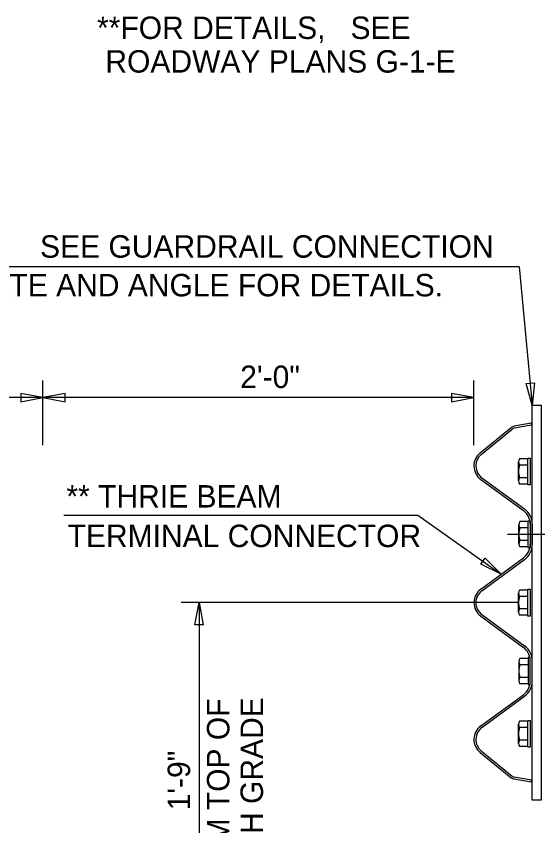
# Model space of a CAD drawing. Extents: x 0 to 22.7, y 0 to 15.7.
# Drawn here: x 15.756 to 18.176, y 5.483 to 9.243 of the extents above; entities that cross this region are included whole.
import ezdxf

# ---------------------------------------------------------------- set-up
doc = ezdxf.new("R2010")
doc.units = 0
for name, color, linetype in [('BRDG_ANNO_General-Notes', 7, 'Continuous'), ('BRDG_BASE_Dtlctrln', 7, 'Continuous'), ('BRDG_BASE_Hidden-Line', 7, 'Continuous'), ('BRDG_BASE_Obj-Line', 7, 'Continuous')]:
    doc.layers.add(name, color=color, linetype=linetype)

msp = doc.modelspace()

# ---------------------------------------------------------------- linework, layer by layer
at = {"layer": 'BRDG_ANNO_General-Notes'}
for p, q in [((18.0902, 8.0784), (15.4641, 8.0784)), ((18.0902, 8.0784), (18.1507, 7.4359)), ((15.8799, 7.2515), (15.8799, 7.5514)), ((17.8799, 7.2515), (17.8799, 7.5514)), ((18.1218, 7.537), (18.1604, 7.5406)), ((18.1507, 7.4359), (18.1218, 7.537)), ((18.1604, 7.5406), (18.1507, 7.4359)), ((15.7766, 7.4914), (15.7766, 7.4526)), ((15.8799, 7.472), (15.7766, 7.4914)), ((15.9832, 7.4914), (15.8799, 7.472)), ((15.9832, 7.4526), (15.9832, 7.4914)), ((17.7766, 7.4914), (17.7766, 7.4526)), ((17.8799, 7.472), (17.7766, 7.4914)), ((15.8799, 7.472), (14.3342, 7.472)), ((15.7766, 7.4526), (15.8799, 7.472)), ((17.8799, 7.472), (15.8799, 7.472)), ((15.8799, 7.472), (15.9832, 7.4526)), ((17.7766, 7.4526), (17.8799, 7.472)), ((15.9759, 6.9254), (17.6197, 6.9254)), ((17.6197, 6.9254), (18.007, 6.6519)), ((17.9127, 6.6974), (17.9325, 6.7256)), ((18.007, 6.6519), (17.9127, 6.6974)), ((17.9325, 6.7256), (18.007, 6.6519)), ((16.5849, 6.4159), (16.6043, 6.5193)), ((16.6043, 6.5193), (16.6043, 4.7693)), ((16.6043, 6.5193), (16.6236, 6.4159)), ((16.6236, 6.4159), (16.5849, 6.4159))]:
    msp.add_line(p, q, dxfattribs=at)
at = {"layer": 'BRDG_BASE_Dtlctrln'}
for p, q in [((18.036, 6.837), (18.3921, 6.837)), ((18.0869, 6.5193), (16.5219, 6.5193))]:
    msp.add_line(p, q, dxfattribs=at)
at = {"layer": 'BRDG_BASE_Hidden-Line'}
for p, q in [((18.1299, 7.1872), (18.0916, 7.1872)), ((18.1299, 7.1286), (18.1299, 7.1872)), ((18.0869, 7.1286), (18.0869, 7.173)), ((18.1299, 7.158), (18.0916, 7.158)), ((18.0869, 7.0844), (18.0869, 7.1286)), ((18.1299, 7.0701), (18.1299, 7.1286)), ((18.1299, 7.0994), (18.0916, 7.0994)), ((18.1299, 7.0701), (18.0916, 7.0701)), ((18.0869, 6.5193), (18.0869, 6.5636)), ((18.1299, 6.5779), (18.0916, 6.5779)), ((18.1299, 6.5486), (18.0916, 6.5486)), ((18.1299, 6.5193), (18.1299, 6.5779)), ((18.0869, 6.475), (18.0869, 6.5193)), ((18.1299, 6.4607), (18.1299, 6.5193)), ((18.1299, 6.49), (18.0916, 6.49)), ((18.1299, 6.4607), (18.0916, 6.4607)), ((18.0869, 5.9099), (18.0869, 5.9542)), ((18.1299, 5.9685), (18.0916, 5.9685)), ((18.1299, 5.9099), (18.1299, 5.9685)), ((18.0869, 5.8656), (18.0869, 5.9099)), ((18.1299, 5.9392), (18.0916, 5.9392)), ((18.1299, 5.8513), (18.1299, 5.9099)), ((18.1299, 5.8806), (18.0916, 5.8806)), ((18.1299, 5.8513), (18.0916, 5.8513))]:
    msp.add_line(p, q, dxfattribs=at)
for points in [[(18.1299, 7.1911), (18.1403, 7.1911), (18.1403, 7.0661), (18.1299, 7.0661)], [(18.1299, 6.5818), (18.1403, 6.5818), (18.1403, 6.4568), (18.1299, 6.4568)], [(18.1299, 5.9724), (18.1403, 5.9724), (18.1403, 5.8474), (18.1299, 5.8474)]]:
    msp.add_lwpolyline(points, close=True, dxfattribs=at)
for centre, radius, start, end in [((18.1123, 7.1726), 0.0254, 144.7697, 215.2303), ((18.1816, 7.1287), 0.0946, 161.9685, 198.0316), ((18.1123, 7.0847), 0.0254, 144.7697, 215.2303), ((18.1123, 6.5632), 0.0254, 144.7697, 215.2303), ((18.1816, 6.5193), 0.0946, 161.9685, 198.0316), ((18.1123, 6.4753), 0.0254, 144.7697, 215.2303), ((18.1123, 5.9539), 0.0254, 144.7697, 215.2303), ((18.1816, 5.9099), 0.0946, 161.9685, 198.0316), ((18.1123, 5.866), 0.0254, 144.7697, 215.2303)]:
    msp.add_arc(centre, radius, start, end, dxfattribs=at)
at = {"layer": 'BRDG_BASE_Obj-Line'}
for p, q in [((18.1455, 7.3526), (18.0669, 7.3388)), ((18.1471, 7.3436), (18.067, 7.3295)), ((18.1455, 7.3526), (18.1471, 7.3436)), ((17.9087, 7.2153), (18.0526, 7.3322)), ((17.9143, 7.2081), (18.0568, 7.3247)), ((17.9119, 7.0917), (18.1096, 6.9469)), ((17.9172, 7.099), (18.115, 6.9543)), ((18.1312, 6.8956), (18.0929, 6.8956)), ((18.1312, 6.837), (18.1312, 6.8956)), ((18.1416, 6.8839), (18.1416, 6.7901)), ((18.1507, 6.8839), (18.1507, 6.7901)), ((18.0883, 6.837), (18.0883, 6.8813)), ((18.1312, 6.8663), (18.0929, 6.8663)), ((18.0883, 6.7927), (18.0883, 6.837)), ((18.1312, 6.8077), (18.0929, 6.8077)), ((18.1312, 6.7784), (18.1312, 6.837)), ((18.1312, 6.7784), (18.0929, 6.7784)), ((17.9119, 6.5823), (18.1096, 6.7271)), ((17.9172, 6.5749), (18.115, 6.7197)), ((17.9119, 6.4562), (18.1096, 6.3115)), ((17.9172, 6.4636), (18.115, 6.3189)), ((18.0883, 6.2458), (18.0883, 6.2016)), ((18.1312, 6.2602), (18.0929, 6.2602)), ((18.1312, 6.2602), (18.1312, 6.2016)), ((18.1416, 6.1547), (18.1416, 6.2484)), ((18.1507, 6.1547), (18.1507, 6.2484)), ((18.1312, 6.2308), (18.0929, 6.2308)), ((18.0883, 6.2016), (18.0883, 6.1572)), ((18.1312, 6.1722), (18.0929, 6.1722)), ((18.1312, 6.2016), (18.1312, 6.143)), ((18.1312, 6.143), (18.0929, 6.143)), ((17.9119, 5.9469), (18.1096, 6.0917)), ((17.9172, 5.9395), (18.115, 6.0843)), ((17.9143, 5.8305), (18.0569, 5.7136)), ((17.9087, 5.8232), (18.0526, 5.7063)), ((18.1455, 5.6859), (18.0669, 5.6998)), ((18.1471, 5.6949), (18.067, 5.709)), ((18.1455, 5.6859), (18.1471, 5.6949))]:
    msp.add_line(p, q, dxfattribs=at)
for points in [[(18.1507, 7.4359), (18.1924, 7.4359), (18.1924, 5.6026), (18.1507, 5.6026)], [(18.1312, 6.8995), (18.1417, 6.8995), (18.1417, 6.7745), (18.1312, 6.7745)], [(18.1312, 6.1391), (18.1417, 6.1391), (18.1417, 6.2641), (18.1312, 6.2641)]]:
    msp.add_lwpolyline(points, close=True, dxfattribs=at)
for centre, radius, start, end in [((18.0723, 7.308), 0.0312, 99.9556, 129.1223), ((18.0709, 7.3077), 0.0221, 99.8748, 129.437), ((17.958, 7.1547), 0.0781, 129.1013, 233.7872), ((17.958, 7.1547), 0.069, 129.3016, 233.7787), ((18.0635, 6.8839), 0.0781, 0, 53.7872), ((18.0635, 6.8839), 0.0872, 0, 53.8142), ((18.1137, 6.8809), 0.0254, 144.7697, 215.2303), ((18.1829, 6.837), 0.0946, 161.9685, 198.0316), ((18.1137, 6.7931), 0.0254, 144.7697, 215.2303), ((18.0635, 6.7901), 0.0781, 306.2128, 0), ((18.0635, 6.7901), 0.0872, 306.1858, 0), ((17.958, 6.5193), 0.0781, 126.2128, 233.7872), ((17.958, 6.5193), 0.069, 126.2213, 233.7787), ((18.0635, 6.2485), 0.0872, 360, 53.8142), ((18.0635, 6.2485), 0.0781, 0, 53.7872), ((18.1137, 6.2455), 0.0254, 144.7697, 215.2303), ((18.1829, 6.2016), 0.0946, 161.9684, 198.0315), ((18.1137, 6.1576), 0.0254, 144.7697, 215.2303), ((18.0635, 6.1547), 0.0781, 306.2128, 0), ((18.0635, 6.1547), 0.0872, 306.1858, 0), ((17.958, 5.8839), 0.0781, 126.2128, 230.8987), ((17.958, 5.8839), 0.069, 126.2213, 230.6984), ((18.0723, 5.7306), 0.0312, 230.9446, 260.0808), ((18.0709, 5.7308), 0.0221, 230.8237, 259.9392)]:
    msp.add_arc(centre, radius, start, end, dxfattribs=at)

# ---------------------------------------------------------------- texts
at = {"layer": 'BRDG_ANNO_General-Notes'}
for s, height, p in [('**FOR DETAILS,   SEE', 0.104167, (16.1307, 9.1374)), (' ROADWAY PLANS G-1-E', 0.104167, (16.1307, 8.9812)), ('SEE GUARDRAIL CONNECTION', 0.104167, (15.8662, 8.1215)), ('PLATE AND ANGLE FOR DETAILS.', 0.104167, (15.4609, 7.9419)), ('2\'-0"', 0.10417, (16.7952, 7.5161)), ('** THRIE BEAM', 0.104167, (15.9885, 6.9611)), ('TERMINAL CONNECTOR', 0.104167, (15.9941, 6.7774))]:
    msp.add_text(s, height=height, dxfattribs=at).set_placement(p)
for s, height, p in [('FROM TOP OF', 0.104167, (16.7449, 5.1068)), ('FINISH GRADE', 0.104167, (16.9011, 5.0891)), ('1\'-9"', 0.10417, (16.5626, 5.5545))]:
    msp.add_text(s, height=height, rotation=90, dxfattribs=at).set_placement(p)

doc.saveas('drawing.dxf')
